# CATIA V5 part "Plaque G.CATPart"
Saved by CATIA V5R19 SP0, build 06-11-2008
Part number: Part1
Bounding box of the stored display mesh (mm): x 0 to 300, y 0 to 630, z 0 to 40
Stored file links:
  C:\Users\Hicham57\Desktop\Chassis presse\Plaque G.CATPart
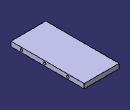
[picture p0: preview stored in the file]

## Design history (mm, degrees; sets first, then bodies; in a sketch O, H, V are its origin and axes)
Body1 (main body)
  Sketch1 on yz-plane, origin (0, 0, 0), H (0, 1, 0), V (0, 0, 1)
    line L1 (0, 0) -> (630, 0)
    line L2 (630, 0) -> (630, 40)
    line L3 (630, 40) -> (0, 40)
    line L4 (0, 40) -> (0, 0)
    length L1 = 630
    length L2 = 40
    horizontal: L1 H, L3 H
    vertical: L2 V, L4 V
  Pad1: profile Sketch1, direction (1, 0, 0), length 300
  Sketch2 on start face of Pad1, origin (0, 0, 0), H (0, -1, 0), V (0, 0, 1)
    circle A1 centre (-490, 20) radius 10
    point P1 (-490, 20)
    circle A2 centre (-290, 20) radius 10
    point P2 (-290, 20)
    circle A3 centre (-90, 20) radius 10
    point P3 (-90, 20)
    reference projected line E1 (-630, 0) -> (-630, 40) from edge [start face of Pad1 | face of Pad1 from Sketch1.L2]
    reference projected line E2 (0, 0) -> (-630, 0) from edge [start face of Pad1 | face of Pad1 from Sketch1.L1]
    reference projected line E3 (0, 0) -> (-630, 0) from edge [start face of Pad1 | face of Pad1 from Sketch1.L1]
    reference projected line E4 (0, 0) -> (-630, 0) from edge [start face of Pad1 | face of Pad1 from Sketch1.L1]
    radius A3 = 10
    radius A2 = 10
    radius A1 = 10
    distance P1 E1 = 140
    distance P2 P1 = 200
    distance P2 P3 = 200
    distance P1 E2 = 20
    distance P2 E3 = 20
    distance P3 E4 = 20
  Pocket1: profile Sketch2, direction (1, 0, 0), length 50
  Sketch3 on end face of Pad1, origin (300, 0, 0), H (0, 1, 0), V (0, 0, 1)
    circle A1 centre (490, 20) radius 10
    circle A2 centre (290, 20) radius 10
    circle A3 centre (90, 20) radius 10
    reference projected circle E1 centre (90, 20) radius 10 from edge [end face of Pocket1 | face of Pocket1 from Sketch2.A3]
    reference projected circle E2 centre (290, 20) radius 10 from edge [end face of Pocket1 | face of Pocket1 from Sketch2.A2]
    reference projected circle E3 centre (490, 20) radius 10 from edge [end face of Pocket1 | face of Pocket1 from Sketch2.A1]
    coincidence: A3 E1, A2 E2, A1 E3
  Pocket2: profile Sketch3, direction (-1, 0, 0), length 50
  Thread1: diameter 22, depth 50, pitch 1, on face of Pocket1 from Sketch2.A2, from start face of Pad1
  Thread2: diameter 22, depth 50, pitch 1, on face of Pocket1 from Sketch2.A1, from start face of Pad1
  Thread3: diameter 22, depth 50, pitch 1, on face of Pocket1 from Sketch2.A3, from start face of Pad1
  Thread4: diameter 22, depth 50, pitch 1, on face of Pocket1 from Sketch2.A1, from start face of Pad1
  Thread5: diameter 22, depth 50, pitch 1, on face of Pocket2 from Sketch3.A1, from end face of Pad1
  Thread6: diameter 22, depth 50, pitch 1, on face of Pocket2 from Sketch3.A2, from end face of Pad1
  Thread7: diameter 22, depth 50, pitch 1, on face of Pocket2 from Sketch3.A3, from end face of Pad1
